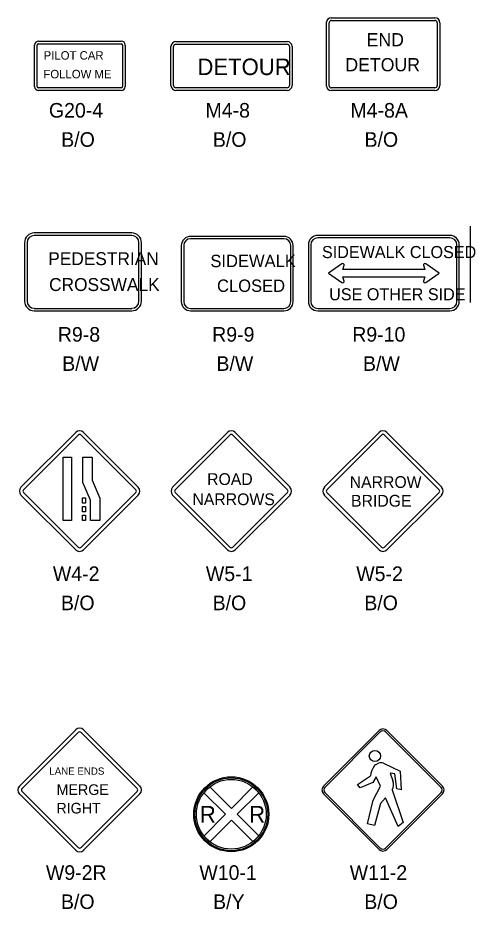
# Model space of a CAD drawing. Extents: x 10034 to 10794, y 10044 to 10499.
# Drawn here: x 10180 to 10288.5, y 10279.6 to 10493.6 of the extents above; entities that cross this region are included whole.
import ezdxf

# ---------------------------------------------------------------- set-up
doc = ezdxf.new("R2010")
doc.units = 0
for name, color, linetype in [('DSDate', 7, 'Continuous'), ('DSIndex', 7, 'Continuous'), ('DSText', 7, 'Continuous'), ('DSTitle', 7, 'Continuous'), ('PlotBorder_dp', 7, 'Continuous')]:
    doc.layers.add(name, color=color, linetype=linetype)

msp = doc.modelspace()

# ---------------------------------------------------------------- linework, layer by layer
at = {"layer": 'DSDate'}
for p, q in [((10254.67, 10489.62), (10254.67, 10492.39)), ((10255.24, 10492.96), (10280.02, 10492.96)), ((10280.58, 10492.39), (10280.58, 10489.47)), ((10254.67, 10477.23), (10254.67, 10489.67)), ((10280.58, 10489.67), (10280.58, 10477.34)), ((10184.94, 10487.37), (10204.74, 10487.37)), ((10217.89, 10487.26), (10244.57, 10487.26)), ((10184.58, 10477.09), (10184.58, 10487.05)), ((10205.1, 10487.05), (10205.1, 10477.09)), ((10217.33, 10477.34), (10217.33, 10486.69)), ((10245.14, 10486.69), (10245.14, 10477.34)), ((10204.74, 10476.77), (10184.94, 10476.77)), ((10244.57, 10476.77), (10217.89, 10476.77)), ((10280.02, 10476.78), (10255.12, 10476.78))]:
    msp.add_line(p, q, dxfattribs=at)
for points in [[(10207.27, 10441.33), (10183.9, 10441.33)], [(10243.77, 10440.54), (10221.42, 10440.54)], [(10182.17, 10439.59), (10182.17, 10425.57)], [(10209.01, 10425.57), (10209.01, 10439.59)], [(10219.76, 10438.88), (10219.76, 10425.46)], [(10245.43, 10425.46), (10245.43, 10438.88)], [(10183.9, 10423.83), (10207.27, 10423.83)], [(10221.42, 10423.81), (10243.77, 10423.81)]]:
    msp.add_lwpolyline(points, dxfattribs=at)
for centre, radius, start, end in [((10255.23, 10492.4), 0.566, 90, 180), ((10280.02, 10492.4), 0.566, 0, 90), ((10217.89, 10486.69), 0.566, 90, 180), ((10244.57, 10486.69), 0.566, 0, 90), ((10217.89, 10477.34), 0.566, 180, 270), ((10244.57, 10477.34), 0.566, 270, 0), ((10255.12, 10477.23), 0.453, 180, 270), ((10280.02, 10477.35), 0.566, 270, 0), ((10183.9, 10439.59), 1.73, 90, 180), ((10207.27, 10439.59), 1.73, 0, 90), ((10221.42, 10438.88), 1.66, 90, 180), ((10243.77, 10438.88), 1.66, 0, 90), ((10183.9, 10425.57), 1.73, 180, 270), ((10207.27, 10425.57), 1.73, 270, 0), ((10221.42, 10425.47), 1.66, 180, 270), ((10243.77, 10425.47), 1.66, 270, 0)]:
    msp.add_arc(centre, radius, start, end, dxfattribs=at)
for centre, major_axis, start_param, end_param in [((10184.94, 10487.05), (-0.359, 0), 4.712389, 6.283185), ((10204.74, 10487.05), (-0.359, 0), 3.141593, 4.712389), ((10184.94, 10477.09), (-0.359, 0), 0, 1.570796), ((10204.74, 10477.09), (0.359, 0), 4.712389, 6.283185)]:
    msp.add_ellipse(centre, major_axis=major_axis, ratio=0.888888, start_param=start_param, end_param=end_param, dxfattribs=at)
at = {"layer": 'DSIndex'}
for p, q in [((10283.61, 10441.34), (10251.92, 10441.34)), ((10283.61, 10440.77), (10251.92, 10440.77)), ((10249.66, 10439.07), (10249.66, 10425.49)), ((10250.22, 10439.07), (10250.22, 10425.49)), ((10285.3, 10425.49), (10285.3, 10439.07)), ((10285.87, 10425.49), (10285.87, 10439.07)), ((10257.72, 10434.5), (10254.47, 10432.28)), ((10257.93, 10433.13), (10258.24, 10434.17)), ((10277.29, 10434.17), (10277.59, 10433.13)), ((10281.06, 10432.28), (10277.81, 10434.5)), ((10254.47, 10432.28), (10257.72, 10430.07)), ((10277.59, 10433.13), (10257.93, 10433.13)), ((10277.81, 10430.07), (10281.06, 10432.28)), ((10258.24, 10430.39), (10257.93, 10431.43)), ((10257.93, 10431.43), (10277.59, 10431.43)), ((10277.59, 10431.43), (10277.29, 10430.39)), ((10251.92, 10423.8), (10283.61, 10423.8)), ((10251.92, 10423.23), (10283.61, 10423.23)), ((10180.7, 10380.87), (10193.85, 10394.02)), ((10181.31, 10380.28), (10194.44, 10393.41)), ((10195.12, 10393.41), (10208.25, 10380.28)), ((10195.72, 10394.02), (10208.86, 10380.87)), ((10193.85, 10365.86), (10180.7, 10379.01)), ((10194.44, 10366.47), (10181.31, 10379.6)), ((10208.25, 10379.6), (10195.12, 10366.47)), ((10208.86, 10379.01), (10195.72, 10365.86)), ((10266.62, 10322.44), (10253.3, 10309.13)), ((10281.83, 10309.13), (10268.52, 10322.44)), ((10266.93, 10322.12), (10253.62, 10308.81)), ((10281.51, 10308.81), (10268.2, 10322.12)), ((10265.94, 10314.32), (10266.5, 10314.6)), ((10267.67, 10314.6), (10271.68, 10312.71)), ((10270.42, 10312.09), (10269.32, 10312.22)), ((10269.32, 10312.22), (10269.95, 10310.34)), ((10270.89, 10308.42), (10270.42, 10312.09)), ((10271.68, 10312.71), (10271.92, 10308.18)), ((10261.47, 10309.49), (10264.56, 10311.58)), ((10265.17, 10309.95), (10262.08, 10308.68)), ((10265.94, 10311.33), (10265.17, 10309.95)), ((10266.94, 10309.06), (10265.94, 10311.33)), ((10229.78, 10302.34), (10224.61, 10307.51)), ((10231.19, 10303.76), (10226.01, 10308.94)), ((10231.19, 10303.76), (10236.35, 10308.92)), ((10232.6, 10302.34), (10237.78, 10307.52)), ((10253.62, 10307.54), (10266.93, 10294.23)), ((10262.08, 10308.68), (10261.47, 10309.49)), ((10265.24, 10305.71), (10266.94, 10309.06)), ((10268.2, 10294.23), (10281.51, 10307.54)), ((10271.92, 10308.18), (10270.89, 10308.42)), ((10253.3, 10307.22), (10266.62, 10293.91)), ((10263.88, 10300.09), (10265.24, 10305.71)), ((10268.16, 10306.27), (10266.98, 10304.9)), ((10271.22, 10299.39), (10268.16, 10306.27)), ((10268.52, 10293.91), (10281.83, 10307.22)), ((10266.98, 10304.9), (10265.52, 10299.64)), ((10224.62, 10297.18), (10229.78, 10302.34)), ((10231.19, 10302.34), (10231.23, 10302.34)), ((10237.77, 10297.18), (10232.6, 10302.34)), ((10232.61, 10302.35), (10232.62, 10302.36)), ((10225.98, 10295.72), (10231.19, 10300.93)), ((10236.33, 10295.79), (10231.19, 10300.93)), ((10265.52, 10299.64), (10263.88, 10300.09))]:
    msp.add_line(p, q, dxfattribs=at)
for points in [[(10288.48, 10443.58), (10288.48, 10425.21)], [(10269.74, 10308.18), (10272.42, 10300.41), (10271.22, 10299.39)]]:
    msp.add_lwpolyline(points, dxfattribs=at)
for points in [[(10190.8, 10388.06), (10192.85, 10388.06), (10192.85, 10372.88), (10190.8, 10372.88)], [(10195.56, 10388.06), (10197.75, 10388.06), (10197.75, 10382.54), (10199.64, 10378.25), (10199.64, 10372.88), (10197.37, 10372.88), (10197.37, 10377.79), (10195.56, 10381.99)], [(10195.45, 10378.36), (10196.22, 10378.36), (10196.22, 10377.06), (10195.45, 10377.06)], [(10195.45, 10376.25), (10196.22, 10376.25), (10196.22, 10374.95), (10195.45, 10374.95)], [(10195.45, 10374.18), (10196.22, 10374.18), (10196.22, 10372.88), (10195.45, 10372.88)], [(10224.62, 10297.18), (10224.66, 10297.07), (10224.79, 10296.92), (10224.96, 10296.74), (10225.06, 10296.59), (10225.27, 10296.41), (10225.44, 10296.22), (10225.63, 10296.03), (10225.82, 10295.9), (10225.98, 10295.72), (10231.19, 10300.93), (10236.33, 10295.79), (10236.53, 10295.91), (10236.78, 10296.14), (10237.04, 10296.35), (10237.26, 10296.62), (10237.54, 10296.86), (10237.77, 10297.18), (10232.6, 10302.34), (10237.78, 10307.52), (10237.55, 10307.7), (10237.42, 10307.92), (10237.21, 10308.16), (10237.02, 10308.37), (10236.78, 10308.56), (10236.6, 10308.73), (10236.35, 10308.92), (10231.19, 10303.76), (10226.01, 10308.94), (10225.82, 10308.73), (10225.55, 10308.53), (10225.25, 10308.27), (10224.99, 10307.96), (10224.72, 10307.68), (10224.61, 10307.51), (10229.78, 10302.34)]]:
    msp.add_lwpolyline(points, close=True, dxfattribs=at)
for centre, radius in [((10265.63, 10316.33), 1.34), ((10231.17, 10302.35), 9), ((10231.17, 10302.35), 8.75), ((10231.17, 10302.35), 8.37)]:
    msp.add_circle(centre, radius, dxfattribs=at)
for centre, radius, start, end in [((10251.92, 10439.07), 2.26, 90, 180), ((10251.92, 10439.07), 1.7, 90, 180), ((10283.61, 10439.07), 2.26, 0, 90), ((10283.61, 10439.07), 1.7, 0, 90), ((10257.93, 10434.26), 0.318, 343.6989, 132.4092), ((10277.6, 10434.26), 0.318, 47.5908, 196.3011), ((10257.93, 10430.3), 0.318, 227.5908, 16.3011), ((10277.6, 10430.3), 0.318, 163.6989, 312.4092), ((10251.92, 10425.49), 2.26, 180, 270), ((10251.92, 10425.49), 1.7, 180, 270), ((10283.61, 10425.49), 2.26, 270, 0), ((10283.61, 10425.49), 1.7, 270, 0), ((10194.78, 10393.08), 1.32, 45, 135), ((10194.78, 10393.07), 0.478, 45, 135), ((10181.64, 10379.94), 1.32, 135, 225), ((10181.65, 10379.94), 0.478, 135, 225), ((10207.91, 10379.94), 0.478, 315, 45), ((10207.92, 10379.94), 1.32, 315, 45), ((10194.78, 10366.8), 1.32, 225, 315), ((10194.78, 10366.81), 0.478, 225, 315), ((10267.57, 10321.49), 1.34, 45, 135), ((10267.57, 10321.49), 0.896, 45, 135), ((10269.89, 10310.85), 5.38, 143.7968, 172.2325), ((10266.53, 10313.11), 1.34, 116.1532, 136.9703), ((10267.1, 10313.39), 1.34, 64.7035, 116.1532), ((10267.4, 10309.49), 2.69, 330.8347, 18.4267), ((10254.26, 10308.18), 1.34, 135, 225), ((10254.26, 10308.18), 0.896, 135, 225), ((10280.88, 10308.18), 0.896, 315, 45), ((10280.88, 10308.18), 1.34, 315, 45), ((10267.57, 10294.86), 1.34, 225, 315), ((10267.57, 10294.86), 0.896, 225, 315)]:
    msp.add_arc(centre, radius, start, end, dxfattribs=at)
at = {"layer": 'DSText'}
for p, q in [((10255.12, 10493.59), (10280.02, 10493.59)), ((10254.04, 10489.59), (10254.04, 10492.51)), ((10281.21, 10492.39), (10281.21, 10489.55)), ((10254.04, 10477.23), (10254.04, 10489.67)), ((10281.21, 10489.67), (10281.21, 10477.34)), ((10184.94, 10487.99), (10204.74, 10487.99)), ((10217.89, 10487.89), (10244.57, 10487.89)), ((10183.95, 10477.09), (10183.95, 10487.05)), ((10205.73, 10487.05), (10205.73, 10477.09)), ((10216.7, 10477.34), (10216.7, 10486.69)), ((10245.76, 10486.69), (10245.76, 10477.34)), ((10204.74, 10476.15), (10184.94, 10476.15)), ((10244.57, 10476.15), (10217.89, 10476.15)), ((10280.02, 10476.15), (10255.12, 10476.15)), ((10217.09, 10380.87), (10230.24, 10394.02)), ((10232.11, 10394.02), (10245.26, 10380.87)), ((10253.49, 10380.87), (10266.63, 10394.02)), ((10268.5, 10394.02), (10281.65, 10380.87)), ((10230.24, 10365.86), (10217.09, 10379.01)), ((10245.26, 10379.01), (10232.11, 10365.86)), ((10266.63, 10365.86), (10253.49, 10379.01)), ((10281.65, 10379.01), (10268.5, 10365.86)), ((10180.35, 10309.13), (10193.83, 10322.61)), ((10195.74, 10322.61), (10209.22, 10309.13)), ((10193.83, 10293.74), (10180.35, 10307.22)), ((10209.22, 10307.22), (10195.74, 10293.74))]:
    msp.add_line(p, q, dxfattribs=at)
for points in [[(10207.27, 10441.93), (10183.9, 10441.93)], [(10243.77, 10441.11), (10221.42, 10441.11)], [(10181.56, 10439.59), (10181.56, 10425.57)], [(10209.61, 10425.57), (10209.61, 10439.59)], [(10219.18, 10438.88), (10219.18, 10425.46)], [(10246, 10425.46), (10246, 10438.88)], [(10183.9, 10423.23), (10207.27, 10423.23)], [(10221.42, 10423.23), (10243.77, 10423.23)]]:
    msp.add_lwpolyline(points, dxfattribs=at)
for centre, radius, start, end in [((10255.12, 10492.51), 1.08, 90, 180), ((10280.02, 10492.4), 1.19, 0, 90), ((10217.89, 10486.69), 1.19, 90, 180), ((10217.89, 10486.69), 0.566, 90, 180), ((10244.57, 10486.69), 1.19, 0, 90), ((10217.89, 10477.34), 1.19, 180, 270), ((10244.57, 10477.34), 1.19, 270, 0), ((10255.12, 10477.23), 1.08, 180, 270), ((10280.02, 10477.34), 1.19, 270, 0), ((10183.9, 10439.59), 2.34, 90, 180), ((10207.27, 10439.59), 2.34, 0, 90), ((10221.42, 10438.88), 2.24, 90, 180), ((10243.77, 10438.88), 2.24, 0, 90), ((10183.9, 10425.57), 2.34, 180, 270), ((10207.27, 10425.57), 2.34, 270, 0), ((10221.42, 10425.47), 2.24, 180, 270), ((10243.77, 10425.47), 2.24, 270, 0), ((10231.17, 10393.08), 1.32, 45, 135), ((10267.57, 10393.08), 1.32, 45, 135), ((10218.03, 10379.94), 1.32, 135, 225), ((10244.31, 10379.94), 1.32, 315, 45), ((10254.43, 10379.94), 1.32, 135, 225), ((10280.71, 10379.94), 1.32, 315, 45), ((10231.18, 10366.8), 1.32, 225, 315), ((10267.57, 10366.8), 1.32, 225, 315), ((10194.78, 10321.65), 1.36, 45, 135), ((10181.31, 10308.17), 1.36, 135, 225), ((10208.25, 10308.18), 1.36, 315, 45), ((10194.79, 10294.7), 1.36, 225, 315)]:
    msp.add_arc(centre, radius, start, end, dxfattribs=at)
for centre, major_axis, start_param, end_param in [((10184.94, 10487.05), (-0.984, 0), 4.712389, 6.283185), ((10204.74, 10487.05), (-0.984, 0), 3.141593, 4.712389), ((10184.94, 10477.09), (-0.984, 0), 0, 1.570796), ((10204.74, 10477.09), (0.984, 0), 4.712389, 6.283185)]:
    msp.add_ellipse(centre, major_axis=major_axis, ratio=0.959484, start_param=start_param, end_param=end_param, dxfattribs=at)
at = {"layer": 'DSTitle'}
for p, q in [((10217.71, 10380.28), (10230.84, 10393.41)), ((10231.52, 10393.41), (10244.64, 10380.28)), ((10254.1, 10380.28), (10267.23, 10393.41)), ((10267.91, 10393.41), (10281.04, 10380.28)), ((10230.84, 10366.47), (10217.71, 10379.6)), ((10244.64, 10379.6), (10231.52, 10366.47)), ((10267.23, 10366.47), (10254.1, 10379.6)), ((10281.04, 10379.6), (10267.91, 10366.47)), ((10180.98, 10308.52), (10194.44, 10321.98)), ((10195.13, 10321.98), (10208.59, 10308.52)), ((10194.44, 10294.37), (10180.98, 10307.83)), ((10208.59, 10307.83), (10195.13, 10294.37))]:
    msp.add_line(p, q, dxfattribs=at)
for centre, radius, start, end in [((10231.17, 10393.07), 0.478, 45, 135), ((10267.57, 10393.07), 0.478, 45, 135), ((10218.04, 10379.94), 0.478, 135, 225), ((10244.31, 10379.94), 0.478, 315, 45), ((10254.43, 10379.94), 0.478, 135, 225), ((10280.7, 10379.94), 0.478, 315, 45), ((10231.17, 10366.81), 0.478, 225, 315), ((10267.57, 10366.81), 0.478, 225, 315), ((10194.78, 10321.64), 0.49, 45, 135), ((10181.32, 10308.18), 0.49, 135, 225), ((10208.24, 10308.18), 0.49, 315, 45), ((10194.78, 10294.72), 0.49, 225, 315)]:
    msp.add_arc(centre, radius, start, end, dxfattribs=at)

# ---------------------------------------------------------------- texts
at = {"layer": 'DSIndex'}
for s, height, p in [('SIDEWALK CLOSED', 2.8971, (10252.92, 10435.9)), ('USE OTHER SIDE', 2.8971, (10254.65, 10425.76)), ('R9-10', 3.5, (10260.19, 10415.83)), ('B/W', 3.5, (10262.78, 10408.82)), ('W4-2', 3.5, (10188.36, 10358.36)), ('B/O', 3.5, (10190.3, 10351.35)), ('R', 4, (10223.59, 10300.35)), ('R', 4, (10235.42, 10300.35)), ('W10-1', 3.5, (10223.5, 10286.6)), ('W11-2', 3.5, (10259.58, 10286.6)), ('B/Y', 3.5, (10226.8, 10279.61)), ('B/O', 3.5, (10263.08, 10279.61))]:
    msp.add_text(s, height=height, dxfattribs=at).set_placement(p)
at = {"layer": 'PlotBorder_dp'}
for s, height, p in [('END', 3.17, (10263.64, 10486.75)), ('PILOT CAR', 2.038, (10186.14, 10483.54)), ('DETOUR', 3.963, (10223.04, 10479.84)), ('DETOUR', 3.17, (10258.54, 10480.75)), ('FOLLOW ME', 2.038, (10186.08, 10479.05)), ('G20-4', 3.5, (10187.41, 10469.63)), ('M4-8', 3.5, (10224.98, 10469.63)), ('M4-8A', 3.5, (10259.76, 10469.63)), ('B/O', 3.5, (10190.36, 10462.62)), ('B/O', 3.5, (10226.75, 10462.62)), ('B/O', 3.5, (10263.14, 10462.62)), ('PEDESTRIAN', 3.104, (10187.24, 10434.2)), ('SIDEWALK', 2.968, (10226.15, 10433.72)), ('CROSSWALK', 3.104, (10187.45, 10427.99)), ('CLOSED', 2.968, (10227.75, 10427.78)), ('R9-8', 3.5, (10189.55, 10415.83)), ('R9-9', 3.5, (10226.58, 10415.83)), ('B/W', 3.5, (10190.6, 10408.82)), ('B/W', 3.5, (10227.61, 10408.82)), ('ROAD', 2.831, (10225.37, 10381.41)), ('NARROW', 2.831, (10259.58, 10380.7)), ('NARROWS', 2.831, (10221.84, 10376.57)), ('BRIDGE', 2.831, (10259.9, 10376.21)), ('W5-1', 3.5, (10225.07, 10358.36)), ('W5-2', 3.5, (10261.15, 10358.36)), ('B/O', 3.5, (10226.69, 10351.35)), ('B/O', 3.5, (10263.08, 10351.35)), ('LANE ENDS', 1.742, (10187.51, 10311.84)), ('MERGE', 2.553, (10189.26, 10306.99)), ('RIGHT', 2.553, (10189.21, 10302.54)), ('W9-2R', 3.5, (10186.69, 10286.6)), ('B/O', 3.5, (10190.3, 10279.61))]:
    msp.add_text(s, height=height, dxfattribs=at).set_placement(p)

doc.saveas('drawing.dxf')
